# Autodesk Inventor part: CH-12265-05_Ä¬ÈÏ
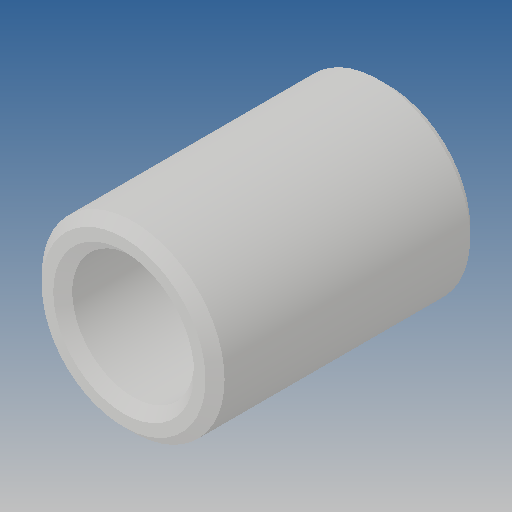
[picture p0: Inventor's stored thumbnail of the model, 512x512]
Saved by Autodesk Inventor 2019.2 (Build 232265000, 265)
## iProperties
Created: 2010-06
Part Number: CH-12265-05_Ä¬ÈÏ
Material: Ogólny
Document SubType Name: Modeling
Designer: CADENGINEERING4
Density: 1 g/cm^3
Appearance: Domyślna
Author: CADENGINEERING4
Revision Number: ÈÎºÎ
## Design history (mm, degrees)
feature "NONE"
node "Bryła1"
